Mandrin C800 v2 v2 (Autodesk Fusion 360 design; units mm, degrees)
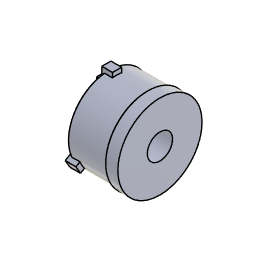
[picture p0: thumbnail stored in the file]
parameter "Rayon" = 30
derived_base_feature "Fonction de base dérivée1"
derived_base_feature "Fonction de base dérivée1" bodies "Corps1"
derived_base_feature "Fonction de base dérivée1" bodies "Corps1"
position "Position1"
position "Position2"
work_plane "Plan de construction1" AlongDistance 0
sketch "Esquisse" plane through (-122, 51.2053, 31.8378) normal (-1, 0, 0) x axis (0, 1, 0)
  circle C1 centre (-51.2053, 31.8378) radius 30
  arc A1 centre (-51.2053, 31.8378) radius 31 clockwise from (-20.6228, 36.9084) to (-40.3053, 2.8173)
  concentric C1 A1
  dimension "d3" diameter C1 = 60 (= "Rayon * 2")
work_plane "Plan de construction1"
work_plane "Plan de construction2"
work_axis "Axe de construction"
work_point "WorkPoint1"
joint "Assembler1" alignOffsetX 30 (= "Rayon") alignOffsetY 0 alignOffsetZ 0
joint "Assembler2" alignOffsetZ 0
joint "Assembler3" alignOffsetZ 0
work_point "WorkPoint1"
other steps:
create_component "CreateComponent2"
create_component "CreateComponent1"
create_component "CreateComponent2"
joint_origin "JointOrigin1"
joint_origin "JointOrigin1"
joint_origin "JointOrigin2"
joint_origin "JointOrigin2"
joint_origin "JointOrigin3"
joint_origin "JointOrigin3"
named bodies: "Corps1"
